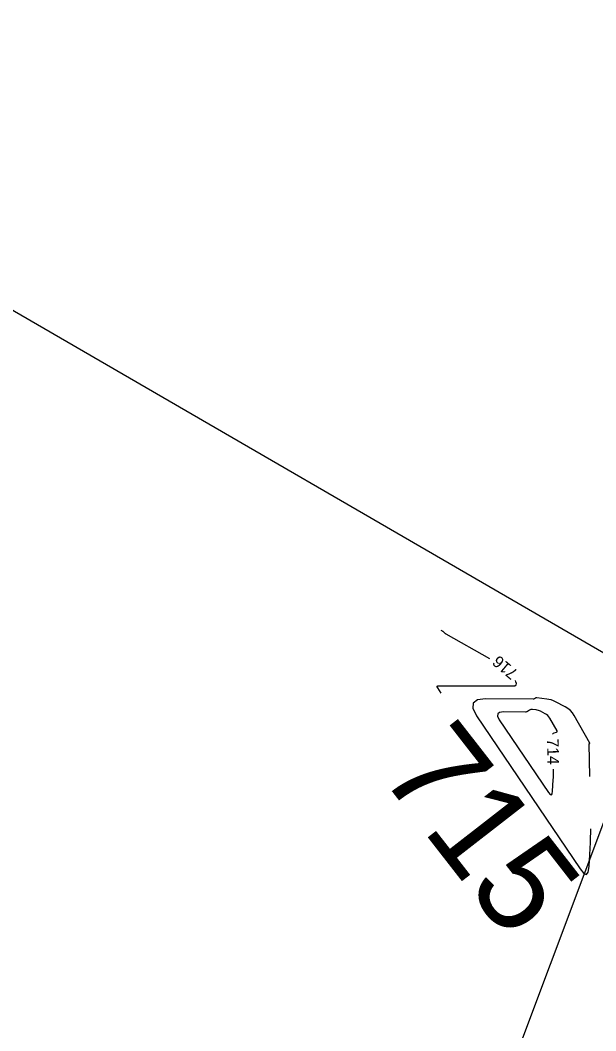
# Model space of a CAD drawing. Extents: x -468548933 to 3387700, y -306089263 to 1207014.
# Drawn here: x 1834987.4 to 1835184.3, y 536152.2 to 536498.1 of the extents above; entities that cross this region are included whole.
import ezdxf

# ---------------------------------------------------------------- set-up
doc = ezdxf.new("R2010")
doc.units = 0
for name, color, linetype in [('DT_X_Contour_Minor', 7, 'Continuous'), ('Level 19', 7, 'Continuous'), ('Level 40', 7, 'Continuous')]:
    doc.layers.add(name, color=color, linetype=linetype)

msp = doc.modelspace()

# ---------------------------------------------------------------- linework, layer by layer
at = {"layer": 'DT_X_Contour_Minor'}
for points in [[(1835148.01, 536279.48), (1835133.14, 536287.94), (1835132.99, 536288.03), (1835132.85, 536288.13), (1835132.71, 536288.24), (1835132.58, 536288.36), (1835132.15, 536288.78), (1835132.07, 536288.85), (1835131.99, 536288.92), (1835131.9, 536288.98), (1835131.8, 536289.03), (1835131.34, 536289.25)], [(1835131.4, 536267.81), (1835130.22, 536269.57), (1835130.05, 536269.9), (1835130.06, 536270.14), (1835130.25, 536270.28), (1835130.62, 536270.32), (1835155.97, 536270.22), (1835156.63, 536270.31), (1835157.02, 536270.58), (1835157.13, 536271.05), (1835156.98, 536271.69), (1835156.84, 536272.06)], [(1835182.23, 536239.26), (1835182.01, 536250.4), (1835182.02, 536250.44), (1835182.03, 536250.47), (1835182.06, 536250.49), (1835182.09, 536250.51), (1835182.23, 536250.54), (1835182.25, 536250.55), (1835182.27, 536250.57), (1835182.27, 536250.59), (1835182.26, 536250.61), (1835176.93, 536260.06), (1835176.31, 536260.99), (1835175.58, 536261.81), (1835174.74, 536262.51), (1835173.79, 536263.1), (1835170.48, 536264.83), (1835169.76, 536265.17), (1835169.03, 536265.43), (1835168.27, 536265.63), (1835167.5, 536265.76), (1835164.08, 536266.18), (1835163.95, 536266.18), (1835163.83, 536266.17), (1835163.71, 536266.13), (1835163.6, 536266.07), (1835163.23, 536265.84), (1835163.15, 536265.79), (1835163.07, 536265.76), (1835162.98, 536265.75), (1835162.89, 536265.74), (1835146.58, 536265.8), (1835143.77, 536265.45), (1835142.32, 536264.38), (1835142.23, 536262.57), (1835143.5, 536260.04)], [(1835143.5, 536260.04), (1835178.91, 536207.59), (1835180.15, 536206.08), (1835181.08, 536205.72), (1835181.69, 536206.51), (1835181.98, 536208.44), (1835182.41, 536216.61), (1835182.49, 536218.36), (1835182.53, 536220.11), (1835182.54, 536221.26)], [(1835169.57, 536253.75), (1835169.58, 536253.8), (1835169.67, 536253.98), (1835169.82, 536254.12), (1835170.04, 536254.21), (1835170.85, 536254.42), (1835170.99, 536254.48), (1835171.06, 536254.57), (1835171.07, 536254.68), (1835171.02, 536254.83), (1835168.55, 536259.2), (1835168.24, 536259.67), (1835167.88, 536260.07), (1835167.47, 536260.42), (1835167, 536260.71), (1835165.36, 536261.56), (1835165.01, 536261.73), (1835164.65, 536261.86), (1835164.27, 536261.96), (1835163.89, 536262.02), (1835162.6, 536262.18), (1835162.34, 536262.19), (1835162.09, 536262.16), (1835161.85, 536262.08), (1835161.63, 536261.96), (1835160.9, 536261.5), (1835160.74, 536261.41), (1835160.57, 536261.35), (1835160.4, 536261.31), (1835160.21, 536261.3), (1835152.7, 536261.33), (1835151.4, 536261.17), (1835150.73, 536260.67), (1835150.69, 536259.84), (1835151.28, 536258.67)], [(1835151.28, 536258.67), (1835168.07, 536233.79), (1835168.66, 536233.08), (1835169.1, 536232.91), (1835169.39, 536233.28), (1835169.52, 536234.19), (1835169.73, 536238.06), (1835169.77, 536238.88), (1835169.79, 536239.71), (1835169.79, 536240.54), (1835169.79, 536241.37), (1835169.78, 536241.76)]]:
    msp.add_lwpolyline(points, dxfattribs=at)
at = {"layer": 'Level 40'}
for p, q in [((1834766.39, 536525.4), (1835190.59, 536279.52)), ((1835150.33, 536125.71), (1835207.87, 536279.41))]:
    msp.add_line(p, q, dxfattribs=at)

# ---------------------------------------------------------------- texts
at = {"layer": 'Level 19'}
for s, height, rotation, p in [('716', 4, 139.9503, (1835157.93, 536275.17)), ('715', 33, 307.8741, (1835109.68, 536240.43)), ('714', 4, 270.9922, (1835167.59, 536252.19))]:
    msp.add_text(s, height=height, rotation=rotation, dxfattribs=at).set_placement(p)

doc.saveas('drawing.dxf')
